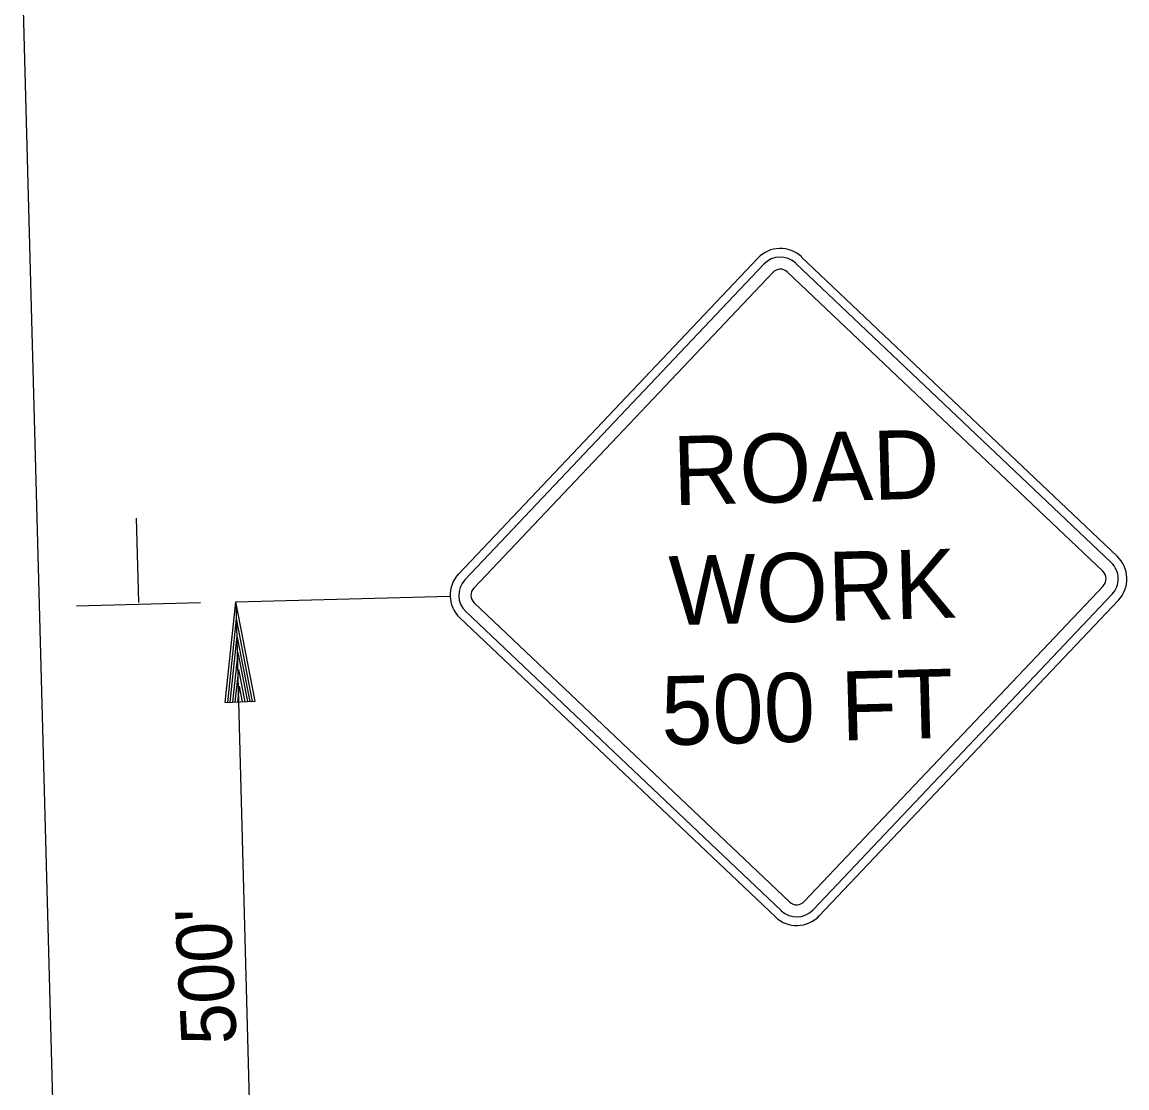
# Model space of a CAD drawing. Extents: x 1930579 to 1931593, y 596452 to 598537.
# Drawn here: x 1930957.7 to 1931077.8, y 597559.3 to 597675.1 of the extents above; entities that cross this region are included whole.
import ezdxf

# ---------------------------------------------------------------- set-up
doc = ezdxf.new("R2010")
doc.units = 0
doc.layers.add('P_TC_Signs_Temporary', color=7, linetype='Continuous')
doc.layers.add('R_Draft', color=7, linetype='Continuous')

msp = doc.modelspace()

# ---------------------------------------------------------------- linework, layer by layer
at = {"layer": 'P_TC_Signs_Temporary'}
for p, q in [((1931005.15, 597615.14), (1931037.65, 597649.44)), ((1931005.83, 597614.5), (1931038.33, 597648.79)), ((1931041.78, 597648.88), (1931076.07, 597616.38)), ((1931042.42, 597649.56), (1931076.72, 597617.06)), ((1931006.78, 597613.59), (1931039.28, 597647.89)), ((1931040.87, 597647.93), (1931075.17, 597615.43)), ((1931075.21, 597613.84), (1931042.71, 597579.54)), ((1931076.16, 597612.94), (1931043.66, 597578.64)), ((1931041.12, 597579.5), (1931006.82, 597612)), ((1931076.84, 597612.29), (1931044.34, 597578)), ((1931039.57, 597577.87), (1931005.28, 597610.37)), ((1931040.22, 597578.55), (1931005.92, 597611.05))]:
    msp.add_line(p, q, dxfattribs=at)
for centre, radius, start, end in [((1931040.1, 597647.12), 3.38, 46.5377, 136.5377), ((1931040.1, 597647.12), 2.44, 46.5377, 136.5377), ((1931040.1, 597647.12), 1.13, 46.5377, 136.5377), ((1931074.39, 597614.61), 2.44, 316.5377, 46.5377), ((1931074.39, 597614.61), 3.38, 316.5377, 46.5377), ((1931007.6, 597612.82), 3.38, 136.5377, 226.5377), ((1931074.39, 597614.61), 1.12, 316.5377, 46.5377), ((1931007.6, 597612.82), 2.44, 136.5377, 226.5377), ((1931007.6, 597612.82), 1.12, 136.5377, 226.5377), ((1931041.89, 597580.32), 1.13, 226.5377, 316.5377), ((1931041.89, 597580.32), 3.38, 226.5377, 316.5377), ((1931041.89, 597580.32), 2.44, 226.5377, 316.5377)]:
    msp.add_arc(centre, radius, start, end, dxfattribs=at)
at = {"layer": 'R_Draft'}
for p, q in [((1930969.35, 597247.87), (1930957.71, 597681.72)), ((1930970.38, 597612.02), (1930970.14, 597621.2)), ((1930980.94, 597612.1), (1931004.22, 597612.73)), ((1930977.09, 597612), (1930963.63, 597611.64)), ((1930979.77, 597601.17), (1930980.94, 597612.1)), ((1930980.94, 597612.1), (1930983.62, 597512.14)), ((1930983.04, 597601.3), (1930980.94, 597612.1)), ((1930980.05, 597601.18), (1930981.02, 597610.29)), ((1930982.76, 597601.29), (1930981.02, 597610.29)), ((1930980.32, 597601.19), (1930981.09, 597608.42)), ((1930982.48, 597601.28), (1930981.09, 597608.42)), ((1930980.59, 597601.2), (1930981.17, 597606.61)), ((1930982.22, 597601.27), (1930981.17, 597606.61)), ((1930980.87, 597601.21), (1930981.25, 597604.77)), ((1930981.93, 597601.26), (1930981.25, 597604.77)), ((1930981.15, 597601.22), (1930981.33, 597602.95)), ((1930981.66, 597601.24), (1930981.33, 597602.95)), ((1930979.77, 597601.17), (1930983.04, 597601.3))]:
    msp.add_line(p, q, dxfattribs=at)

# ---------------------------------------------------------------- texts
at = {"layer": 'P_TC_Signs_Temporary'}
for s, p in [(' ROAD ', (1931025.73, 597622.52)), ('WORK', (1931028.11, 597609.56)), ('500 FT ', (1931027.24, 597596.51))]:
    msp.add_text(s, height=7.5, rotation=1.5377, dxfattribs=at).set_placement(p)
at = {"layer": 'R_Draft'}
msp.add_text("500'", height=6, rotation=92.7681, dxfattribs=at).set_placement((1930981.03, 597564.13))

doc.saveas('drawing.dxf')
